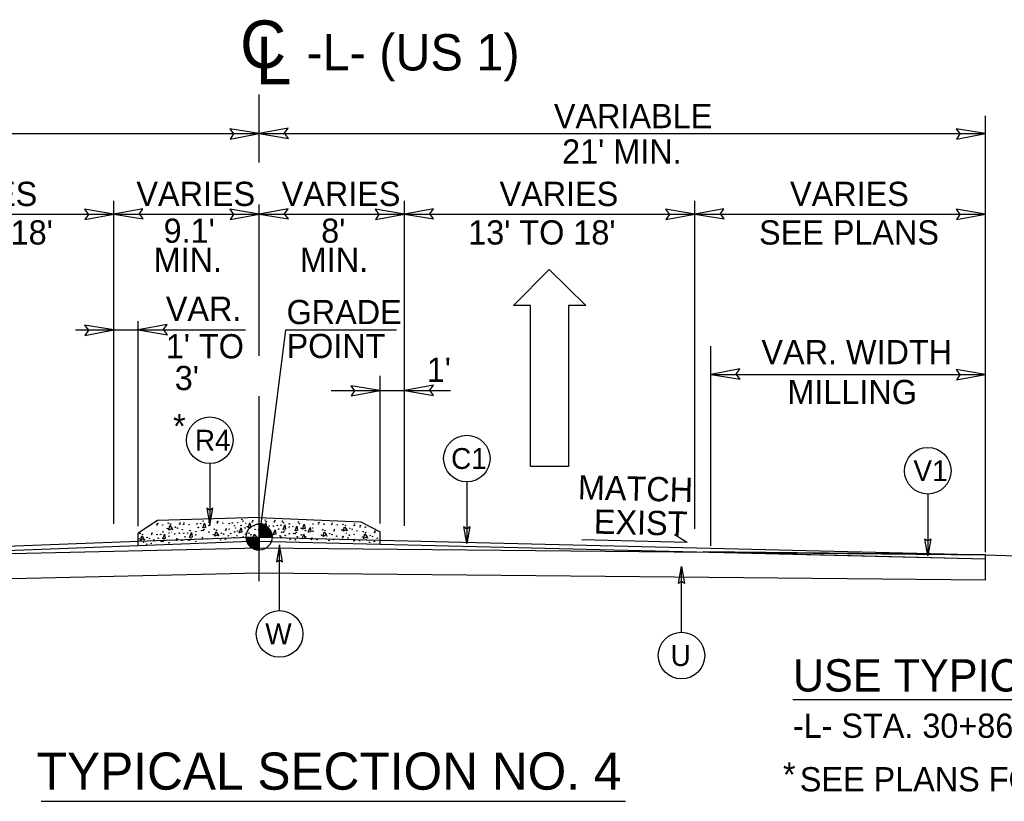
# Model space of a CAD drawing. Extents: x 573748 to 574632, y -54663 to -53209.
# Drawn here: x 573807.9 to 573868.9, y -53656.2 to -53607.8 of the extents above; entities that cross this region are included whole.
import ezdxf

# ---------------------------------------------------------------- set-up
doc = ezdxf.new("R2010")
doc.units = 0
for name, color, linetype in [('Prop Dimension', 7, 'Continuous'), ('Prop Dimension Text', 7, 'Continuous'), ('Prop Lane Arrow CELL', 7, 'Continuous'), ('Prop Terminator CELL', 7, 'Continuous'), ('Typical Arrow Superelevation CELL', 7, 'Continuous'), ('Typical Curb CELL', 7, 'Continuous'), ('Typical Grade Point Symbol CELL', 7, 'Continuous'), ('Typical ID Circle CELL', 7, 'Continuous'), ('Typical Pavement Slope CELL', 7, 'Continuous'), ('Typical Terminator CELL', 7, 'Continuous'), ('Typical Text Centerline CELL', 7, 'Continuous'), ('Typical Text General CELL', 7, 'Continuous'), ('Typical Text ID Circle CELL', 7, 'Continuous'), ('Typical Text Label CELL', 7, 'Continuous')]:
    doc.layers.add(name, color=color, linetype=linetype)

# ---------------------------------------------------------------- blocks, each defined once
blk = doc.blocks.new('CENTERLINE TEXT CL')
at = {"layer": 'Typical Text Centerline CELL'}
blk.add_text('C', height=1.64, dxfattribs=at).set_placement((-0.546, -0.261))
blk.add_text('L', height=1.641, rotation=359.9469, dxfattribs=at).set_placement((-0.001, -0.821))

msp = doc.modelspace()

# ---------------------------------------------------------------- linework, layer by layer
at = {"layer": 'Prop Dimension'}
for p, q in [((573822.721, -53616.626), (573822.721, -53612.419)), ((573867.721, -53640.778), (573867.721, -53613.746)), ((573867.721, -53638.046), (573867.721, -53613.746)), ((573777.721, -53614.846), (573822.721, -53614.846)), ((573822.721, -53614.846), (573867.721, -53614.846)), ((573813.721, -53639.007), (573813.721, -53619.001)), ((573831.721, -53639.143), (573831.721, -53619.001)), ((573849.721, -53639.33), (573849.721, -53619.001)), ((573822.721, -53628.608), (573822.721, -53619.243)), ((573795.721, -53619.827), (573813.721, -53619.827)), ((573813.721, -53619.827), (573822.721, -53619.827)), ((573822.721, -53619.827), (573831.721, -53619.827)), ((573831.721, -53619.827), (573849.721, -53619.827)), ((573849.721, -53619.827), (573867.721, -53619.827)), ((573811.343, -53627.007), (573821.876, -53627.007)), ((573815.221, -53639.155), (573815.221, -53626.465)), ((573850.708, -53640.379), (573850.708, -53628.013)), ((573830.221, -53639.004), (573830.221, -53629.853)), ((573850.708, -53629.758), (573867.721, -53629.758)), ((573822.721, -53642.56), (573822.721, -53631.099)), ((573827.184, -53630.764), (573834.582, -53630.764)), ((573822.721, -53638.617), (573816.429, -53638.815)), ((573822.721, -53638.617), (573829.014, -53638.889)), ((573816.429, -53638.815), (573815.221, -53639.605)), ((573829.014, -53638.889), (573830.221, -53639.506)), ((573815.221, -53640.375), (573815.221, -53639.605)), ((573830.221, -53640.276), (573830.221, -53639.506)), ((573822.721, -53640.094), (573815.221, -53640.375)), ((573822.721, -53640.094), (573830.221, -53640.276)), ((573777.721, -53641.521), (573822.721, -53640.499)), ((573822.721, -53640.499), (573867.721, -53640.927)), ((573867.721, -53640.927), (573850.242, -53640.761)), ((573850.242, -53640.761), (573867.721, -53641.184)), ((573867.721, -53640.927), (573883.644, -53641.498)), ((573867.721, -53642.484), (573867.721, -53640.927)), ((573867.721, -53641.184), (573867.721, -53640.927)), ((573777.721, -53643.077), (573822.721, -53642.056)), ((573822.721, -53642.056), (573867.721, -53642.484))]:
    msp.add_line(p, q, dxfattribs=at)
msp.add_lwpolyline([(573831.242, -53627.01), (573824.353, -53627.01), (573822.721, -53639.837)], dxfattribs=at)
at = {"layer": 'Prop Lane Arrow CELL'}
for p, q in [((573838.477, -53625.497), (573840.686, -53623.253)), ((573840.686, -53623.253), (573842.966, -53625.497)), ((573839.546, -53625.497), (573838.477, -53625.497)), ((573839.546, -53635.472), (573839.546, -53625.497)), ((573842.966, -53625.497), (573841.897, -53625.497)), ((573841.897, -53625.497), (573841.897, -53635.472)), ((573841.897, -53635.472), (573839.546, -53635.472))]:
    msp.add_line(p, q, dxfattribs=at)
at = {"layer": 'Prop Terminator CELL'}
for points in [[(573820.925, -53615.179), (573822.721, -53614.846), (573820.907, -53614.549), (573821.141, -53614.866)], [(573824.518, -53614.513), (573822.721, -53614.846), (573824.536, -53615.143), (573824.302, -53614.825)], [(573865.925, -53615.179), (573867.721, -53614.846), (573865.907, -53614.549), (573866.141, -53614.866)], [(573811.925, -53620.161), (573813.721, -53619.827), (573811.907, -53619.531), (573812.141, -53619.848)], [(573815.518, -53619.494), (573813.721, -53619.827), (573815.536, -53620.124), (573815.302, -53619.807)], [(573820.925, -53620.161), (573822.721, -53619.827), (573820.907, -53619.531), (573821.141, -53619.848)], [(573824.518, -53619.494), (573822.721, -53619.827), (573824.536, -53620.124), (573824.302, -53619.807)], [(573829.925, -53620.161), (573831.721, -53619.827), (573829.907, -53619.531), (573830.141, -53619.848)], [(573833.518, -53619.494), (573831.721, -53619.827), (573833.536, -53620.124), (573833.302, -53619.807)], [(573847.925, -53620.161), (573849.721, -53619.827), (573847.907, -53619.531), (573848.141, -53619.848)], [(573851.518, -53619.494), (573849.721, -53619.827), (573851.536, -53620.124), (573851.302, -53619.807)], [(573865.925, -53620.161), (573867.721, -53619.827), (573865.907, -53619.531), (573866.141, -53619.848)], [(573811.925, -53627.341), (573813.721, -53627.007), (573811.907, -53626.71), (573812.141, -53627.028)], [(573817.018, -53626.674), (573815.221, -53627.007), (573817.036, -53627.304), (573816.802, -53626.987)], [(573852.504, -53629.425), (573850.708, -53629.758), (573852.522, -53630.055), (573852.288, -53629.738)], [(573865.925, -53630.092), (573867.721, -53629.758), (573865.907, -53629.462), (573866.141, -53629.779)], [(573828.425, -53631.097), (573830.221, -53630.764), (573828.407, -53630.467), (573828.641, -53630.784)], [(573833.518, -53630.431), (573831.721, -53630.764), (573833.536, -53631.061), (573833.302, -53630.744)]]:
    msp.add_lwpolyline(points, close=True, dxfattribs=at)
at = {"layer": 'Typical Arrow Superelevation CELL'}
for q in [(573848.465, -53639.688), (573842.724, -53640.01)]:
    msp.add_line((573849.247, -53640.164), q, dxfattribs=at)
at = {"layer": 'Typical Curb CELL'}
for p, q in [((573817.122, -53639.406), (573817.199, -53639.127)), ((573817.199, -53639.127), (573817.333, -53639.3)), ((573819.239, -53639.272), (573819.347, -53638.979)), ((573819.393, -53639.249), (573819.239, -53639.272)), ((573819.347, -53638.979), (573819.393, -53639.249)), ((573821.493, -53639.564), (573821.601, -53639.271)), ((573821.601, -53639.271), (573821.648, -53639.541)), ((573822.034, -53639.252), (573822.142, -53638.959)), ((573822.188, -53639.229), (573822.034, -53639.252)), ((573822.142, -53638.959), (573822.188, -53639.229)), ((573823.021, -53639.251), (573823.128, -53638.958)), ((573823.175, -53639.228), (573823.021, -53639.251)), ((573823.128, -53638.958), (573823.175, -53639.228)), ((573824.209, -53639.372), (573824.316, -53639.079)), ((573824.316, -53639.079), (573824.363, -53639.349)), ((573824.95, -53639.459), (573825.057, -53639.166)), ((573825.057, -53639.166), (573825.104, -53639.436)), ((573825.411, -53639.338), (573825.519, -53639.045)), ((573825.519, -53639.045), (573825.566, -53639.315)), ((573825.77, -53639.54), (573825.878, -53639.247)), ((573825.878, -53639.247), (573825.925, -53639.517)), ((573827.937, -53639.479), (573828.014, -53639.2)), ((573828.014, -53639.2), (573828.148, -53639.373)), ((573815.372, -53640.04), (573815.449, -53639.761)), ((573815.449, -53639.761), (573815.583, -53639.934)), ((573816.752, -53639.941), (573816.859, -53639.648)), ((573816.859, -53639.648), (573816.906, -53639.918)), ((573817.333, -53639.3), (573817.122, -53639.406)), ((573818.418, -53639.856), (573818.525, -53639.563)), ((573818.572, -53639.833), (573818.418, -53639.856)), ((573818.525, -53639.563), (573818.572, -53639.833)), ((573819.97, -53639.782), (573820.047, -53639.503)), ((573820.181, -53639.676), (573819.97, -53639.782)), ((573820.047, -53639.503), (573820.181, -53639.676)), ((573821.648, -53639.541), (573821.493, -53639.564)), ((573822.342, -53639.943), (573822.419, -53639.664)), ((573822.553, -53639.837), (573822.342, -53639.943)), ((573822.419, -53639.664), (573822.553, -53639.837)), ((573823.601, -53639.688), (573823.709, -53639.395)), ((573823.755, -53639.665), (573823.601, -53639.688)), ((573823.709, -53639.395), (573823.755, -53639.665)), ((573824.363, -53639.349), (573824.209, -53639.372)), ((573825.104, -53639.436), (573824.95, -53639.459)), ((573825.392, -53639.942), (573825.5, -53639.649)), ((573825.566, -53639.315), (573825.411, -53639.338)), ((573825.5, -53639.649), (573825.546, -53639.919)), ((573825.925, -53639.517), (573825.77, -53639.54)), ((573826.685, -53639.809), (573826.762, -53639.53)), ((573826.896, -53639.703), (573826.685, -53639.809)), ((573826.762, -53639.53), (573826.896, -53639.703)), ((573828.148, -53639.373), (573827.937, -53639.479)), ((573829.196, -53639.924), (573829.273, -53639.645)), ((573829.407, -53639.818), (573829.196, -53639.924)), ((573829.273, -53639.645), (573829.407, -53639.818)), ((573815.583, -53639.934), (573815.372, -53640.04)), ((573816.906, -53639.918), (573816.752, -53639.941)), ((573825.546, -53639.919), (573825.392, -53639.942))]:
    msp.add_line(p, q, dxfattribs=at)
for centre in [(573816.401, -53639.081), (573816.429, -53638.993), (573816.739, -53639.09), (573817.095, -53638.979), (573817.242, -53639.038), (573817.525, -53639.223), (573817.671, -53639.281), (573817.801, -53639.041), (573817.829, -53638.953), (573818.036, -53639.057), (573818.064, -53638.97), (573818.374, -53639.067), (573818.877, -53639.017), (573818.957, -53639.242), (573819.102, -53639.006), (573819.256, -53638.851), (573819.615, -53639.119), (573819.622, -53638.916), (573820.132, -53638.958), (573820.16, -53638.87), (573820.47, -53638.967), (573820.872, -53639.003), (573821.056, -53638.961), (573821.198, -53639.135), (573821.26, -53639.274), (573821.397, -53638.944), (573821.599, -53639.115), (573821.648, -53638.745), (573821.716, -53638.843), (573821.849, -53639.269), (573821.897, -53638.986), (573821.998, -53639.19), (573822.301, -53638.896), (573822.329, -53638.809), (573822.414, -53639.136), (573822.721, -53638.993), (573822.921, -53639.01), (573823.099, -53638.783), (573823.168, -53638.881), (573823.331, -53639.157), (573823.605, -53639.156), (573823.665, -53638.896), (573823.693, -53638.809), (573823.847, -53639.116), (573824.072, -53639.105), (573824.157, -53638.852), (573824.226, -53638.95), (573824.585, -53639.218), (573824.592, -53639.015), (573824.813, -53639.192), (573825.145, -53638.914), (573825.214, -53639.013), (573825.326, -53639.292), (573826.038, -53639.276), (573826.055, -53639.028), (573826.397, -53639.028), (573826.425, -53638.941), (573826.735, -53639.038), (573827.222, -53639.068), (573827.25, -53638.981), (573827.56, -53639.078), (573827.91, -53639.052), (573828.057, -53639.111), (573828.616, -53639.114), (573828.644, -53639.026), (573828.968, -53639.213), (573828.996, -53639.125), (573829.305, -53639.223), (573815.346, -53639.614), (573815.493, -53639.672), (573815.775, -53639.857), (573816.052, -53639.675), (573816.08, -53639.588), (573816.389, -53639.685), (573816.615, -53639.674), (573816.768, -53639.519), (573817.039, -53639.313), (573817.128, -53639.787), (573817.135, -53639.584), (573817.353, -53639.367), (573817.491, -53639.643), (573817.783, -53639.595), (573817.962, -53639.378), (573818.055, -53639.6), (573818.136, -53639.826), (573818.281, -53639.589), (573818.434, -53639.434), (573818.794, -53639.702), (573818.801, -53639.5), (573819.149, -53639.438), (573819.216, -53639.854), (573819.246, -53639.438), (573819.309, -53639.361), (573819.62, -53639.528), (573819.887, -53639.689), (573819.944, -53639.356), (573820.09, -53639.414), (573820.201, -53639.743), (573820.373, -53639.599), (573820.519, -53639.658), (573820.649, -53639.417), (573820.677, -53639.33), (573820.81, -53639.754), (573820.867, -53639.35), (573820.959, -53639.623), (573821.172, -53639.872), (573821.203, -53639.513), (573821.343, -53639.756), (573821.395, -53639.462), (573821.732, -53639.813), (573821.883, -53639.656), (573822.09, -53639.591), (573822.214, -53639.696), (573822.464, -53639.358), (573822.684, -53639.389), (573822.774, -53639.796), (573822.787, -53639.643), (573822.957, -53639.398), (573823.007, -53639.764), (573823.079, -53639.842), (573823.118, -53639.536), (573823.345, -53639.782), (573823.41, -53639.489), (573823.524, -53639.722), (573823.597, -53639.875), (573823.927, -53639.341), (573824.008, -53639.765), (573824.08, -53639.843), (573824.119, -53639.537), (573824.216, -53639.537), (573824.279, -53639.46), (573824.342, -53639.734), (573824.59, -53639.628), (573824.86, -53639.624), (573824.957, -53639.624), (573825.02, -53639.548), (573825.083, -53639.822), (573825.33, -53639.702), (573825.583, -53639.43), (573825.608, -53639.818), (573825.991, -53639.898), (573826.066, -53639.474), (573826.603, -53639.716), (573826.659, -53639.383), (573826.806, -53639.441), (573826.917, -53639.77), (573827.088, -53639.626), (573827.235, -53639.685), (573827.365, -53639.444), (573827.393, -53639.357), (573827.525, -53639.781), (573827.854, -53639.386), (573827.893, -53639.88), (573827.921, -53639.793), (573828.168, -53639.44), (573828.231, -53639.89), (573828.306, -53639.716), (573828.339, -53639.296), (573828.486, -53639.354), (573828.598, -53639.668), (573828.776, -53639.451), (573829.113, -53639.832), (573829.169, -53639.498), (573829.316, -53639.557), (573829.427, -53639.885), (573829.599, -53639.741), (573829.745, -53639.8), (573829.875, -53639.559), (573829.903, -53639.472), (573830.036, -53639.896), (573815.29, -53639.947), (573815.604, -53640.001), (573815.742, -53640.277), (573815.922, -53639.916), (573816.033, -53640.23), (573816.212, -53640.012), (573816.47, -53639.91), (573816.662, -53640.106), (573816.759, -53640.106), (573816.822, -53640.03), (573817.133, -53640.197), (573817.606, -53640.033), (573817.635, -53639.946), (573817.944, -53640.043), (573818.328, -53640.022), (573818.425, -53640.022), (573818.488, -53639.945), (573818.798, -53640.112), (573819.188, -53639.941), (573819.525, -53639.951), (573820.339, -53640.019), (573820.631, -53639.972), (573824.631, -53639.997), (573824.659, -53639.909), (573824.968, -53640.006), (573825.963, -53639.985), (573826.301, -53639.995), (573827.055, -53640.046), (573827.346, -53639.999), (573828.604, -53640.064), (573828.632, -53639.977), (573828.941, -53640.074), (573829.565, -53640.161), (573829.857, -53640.114)]:
    msp.add_ellipse(centre, major_axis=(0.0001, 0.0192), ratio=0.533333, dxfattribs=at)
for centre in [(573817.305, -53639.548), (573828.12, -53639.621), (573815.556, -53640.182), (573820.154, -53639.925), (573826.869, -53639.951), (573829.379, -53640.067)]:
    msp.add_ellipse(centre, major_axis=(-0.0001, -0.0219), ratio=0.533333, start_param=2.050606, end_param=4.270718, dxfattribs=at)
at = {"layer": 'Typical Grade Point Symbol CELL'}
for p, q in [((573822.721, -53639.837), (573822.721, -53639.031)), ((573821.916, -53639.837), (573822.721, -53639.837)), ((573822.719, -53640.643), (573822.721, -53639.837)), ((573822.721, -53639.837), (573822.719, -53640.643)), ((573823.527, -53639.837), (573822.721, -53639.837))]:
    msp.add_line(p, q, dxfattribs=at)
for points in [[(573822.728, -53639.031), (573822.728, -53639.031), (573822.728, -53639.837)], [(573822.745, -53639.031), (573822.745, -53639.837)], [(573822.761, -53639.033), (573822.761, -53639.837)], [(573822.777, -53639.033), (573822.777, -53639.837)], [(573822.793, -53639.035), (573822.793, -53639.837)], [(573822.809, -53639.037), (573822.809, -53639.837)], [(573822.825, -53639.038), (573822.825, -53639.837)], [(573822.841, -53639.04), (573822.841, -53639.837)], [(573822.857, -53639.042), (573822.857, -53639.837)], [(573822.873, -53639.046), (573822.873, -53639.837)], [(573822.89, -53639.049), (573822.89, -53639.837)], [(573822.906, -53639.053), (573822.906, -53639.837)], [(573822.922, -53639.056), (573822.922, -53639.837)], [(573822.938, -53639.062), (573822.938, -53639.837)], [(573822.954, -53639.065), (573822.954, -53639.837)], [(573822.97, -53639.071), (573822.97, -53639.837)], [(573822.986, -53639.076), (573822.986, -53639.837)], [(573823.002, -53639.081), (573823.002, -53639.837)], [(573823.018, -53639.089), (573823.018, -53639.837)], [(573823.035, -53639.096), (573823.035, -53639.837)], [(573823.051, -53639.103), (573823.051, -53639.837)], [(573823.067, -53639.11), (573823.067, -53639.837)], [(573823.083, -53639.117), (573823.083, -53639.837)], [(573823.099, -53639.126), (573823.099, -53639.837)], [(573823.115, -53639.135), (573823.115, -53639.837)], [(573823.131, -53639.144), (573823.131, -53639.837)], [(573823.147, -53639.153), (573823.147, -53639.837)], [(573823.163, -53639.164), (573823.163, -53639.837)], [(573823.18, -53639.175), (573823.18, -53639.837)], [(573823.196, -53639.187), (573823.196, -53639.837)], [(573823.212, -53639.198), (573823.212, -53639.837)], [(573823.228, -53639.21), (573823.228, -53639.837)], [(573823.244, -53639.225), (573823.244, -53639.837)], [(573823.26, -53639.239), (573823.26, -53639.837)], [(573823.276, -53639.253), (573823.276, -53639.837)], [(573823.292, -53639.269), (573823.292, -53639.837)], [(573821.919, -53639.837), (573821.919, -53639.925)], [(573821.935, -53639.837), (573821.935, -53640.02)], [(573821.951, -53639.837), (573821.951, -53640.077)], [(573821.968, -53639.837), (573821.968, -53640.125)], [(573821.984, -53639.837), (573821.984, -53640.163)], [(573822, -53639.837), (573822, -53640.197)], [(573822.016, -53639.837), (573822.016, -53640.227)], [(573822.032, -53639.837), (573822.032, -53640.256)], [(573822.048, -53639.837), (573822.048, -53640.281)], [(573822.064, -53639.837), (573822.064, -53640.304)], [(573822.08, -53639.837), (573822.08, -53640.326)], [(573822.096, -53639.837), (573822.096, -53640.345)], [(573822.113, -53639.837), (573822.113, -53640.365)], [(573822.129, -53639.837), (573822.129, -53640.383)], [(573822.145, -53639.837), (573822.145, -53640.401)], [(573822.161, -53639.837), (573822.161, -53640.417)], [(573822.177, -53639.837), (573822.177, -53640.431)], [(573822.193, -53639.837), (573822.193, -53640.446)], [(573822.209, -53639.837), (573822.209, -53640.46)], [(573822.225, -53639.837), (573822.225, -53640.472)], [(573822.241, -53639.837), (573822.241, -53640.485)], [(573822.258, -53639.837), (573822.258, -53640.496)], [(573822.274, -53639.837), (573822.274, -53640.507)], [(573822.29, -53639.837), (573822.29, -53640.517)], [(573822.306, -53639.837), (573822.306, -53640.528)], [(573822.322, -53639.837), (573822.322, -53640.537)], [(573822.338, -53639.837), (573822.338, -53640.546)], [(573822.354, -53639.837), (573822.354, -53640.555)], [(573822.37, -53639.837), (573822.37, -53640.562)], [(573822.387, -53639.837), (573822.387, -53640.569)], [(573822.403, -53639.837), (573822.403, -53640.576)], [(573822.419, -53639.837), (573822.419, -53640.583)], [(573822.435, -53639.837), (573822.435, -53640.591)], [(573822.451, -53639.837), (573822.451, -53640.596)], [(573822.467, -53639.837), (573822.467, -53640.601)], [(573822.483, -53639.837), (573822.483, -53640.607)], [(573822.499, -53639.837), (573822.499, -53640.61)], [(573822.515, -53639.837), (573822.515, -53640.616)], [(573822.532, -53639.837), (573822.532, -53640.619)], [(573822.548, -53639.837), (573822.548, -53640.623)], [(573822.564, -53639.837), (573822.564, -53640.626)], [(573822.58, -53639.837), (573822.58, -53640.63)], [(573822.596, -53639.837), (573822.596, -53640.632)], [(573822.612, -53639.837), (573822.612, -53640.635)], [(573822.628, -53639.837), (573822.628, -53640.637)], [(573822.644, -53639.837), (573822.644, -53640.639)], [(573822.66, -53639.837), (573822.66, -53640.641)], [(573822.677, -53639.837), (573822.677, -53640.641)], [(573822.693, -53639.837), (573822.693, -53640.643)], [(573822.709, -53639.837), (573822.709, -53640.643), (573822.709, -53640.643)], [(573823.308, -53639.286), (573823.308, -53639.837)], [(573823.325, -53639.303), (573823.325, -53639.837)], [(573823.341, -53639.323), (573823.341, -53639.837)], [(573823.357, -53639.343), (573823.357, -53639.837)], [(573823.373, -53639.364), (573823.373, -53639.837)], [(573823.389, -53639.388), (573823.389, -53639.837)], [(573823.405, -53639.413), (573823.405, -53639.837)], [(573823.421, -53639.439), (573823.421, -53639.837)], [(573823.437, -53639.468), (573823.437, -53639.837)], [(573823.453, -53639.502), (573823.453, -53639.837)], [(573823.47, -53639.54), (573823.47, -53639.837)], [(573823.486, -53639.585), (573823.486, -53639.837)], [(573823.502, -53639.64), (573823.502, -53639.837)], [(573823.518, -53639.722), (573823.518, -53639.837)]]:
    msp.add_lwpolyline(points, dxfattribs=at)
msp.add_circle((573822.72, -53639.837), 0.806, dxfattribs=at)
for start, end in [(359.99048, 89.99048), (179.99048, 269.99048)]:
    msp.add_arc((573822.72, -53639.837), 0.806, start, end, dxfattribs=at)
at = {"layer": 'Typical ID Circle CELL'}
for p, q in [((573819.666, -53635.284), (573819.666, -53639.11)), ((573835.591, -53636.416), (573835.591, -53640.243)), ((573864.153, -53637.17), (573864.153, -53640.997)), ((573823.99, -53644.395), (573823.99, -53640.312)), ((573848.891, -53645.738), (573848.891, -53641.655))]:
    msp.add_line(p, q, dxfattribs=at)
for centre in [(573819.666, -53633.841), (573835.591, -53634.974), (573864.153, -53635.728), (573823.99, -53645.838), (573848.891, -53647.181)]:
    msp.add_circle(centre, 1.443, dxfattribs=at)
at = {"layer": 'Typical Pavement Slope CELL'}
for p, q in [((573822.721, -53639.837), (573815.221, -53640.118)), ((573822.721, -53639.837), (573830.221, -53640.019)), ((573815.221, -53640.118), (573777.721, -53641.521)), ((573815.221, -53640.375), (573777.721, -53641.778)), ((573830.221, -53640.019), (573867.721, -53640.927)), ((573830.221, -53640.276), (573867.721, -53641.184))]:
    msp.add_line(p, q, dxfattribs=at)
at = {"layer": 'Typical Terminator CELL'}
for points in [[(573819.485, -53638.056), (573819.666, -53639.11), (573819.854, -53638.05), (573819.666, -53638.185)], [(573835.773, -53639.188), (573835.591, -53640.243), (573835.403, -53639.182), (573835.591, -53639.317)], [(573824.171, -53641.366), (573823.99, -53640.312), (573823.802, -53641.372), (573823.99, -53641.237)], [(573864.335, -53639.942), (573864.153, -53640.997), (573863.965, -53639.936), (573864.153, -53640.071)], [(573848.709, -53642.709), (573848.891, -53641.655), (573849.078, -53642.715), (573848.891, -53642.581)]]:
    msp.add_lwpolyline(points, close=True, dxfattribs=at)
at = {"layer": 'Typical Text General CELL'}
msp.add_line((573855.791, -53649.901), (573894.17, -53649.901), dxfattribs=at)
at = {"layer": 'Typical Text Label CELL'}
msp.add_line((573809.221, -53656.206), (573845.428, -53656.206), dxfattribs=at)

# ---------------------------------------------------------------- block references
at = {"layer": 'Prop Dimension', "xscale": 1.8000000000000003, "yscale": 1.8000000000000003}
msp.add_blockref('CENTERLINE TEXT CL', (573822.525, -53610.314), dxfattribs=at)

# ---------------------------------------------------------------- texts
at = {"layer": 'Prop Dimension Text'}
for s, height, p in [('-L- (US 1)', 2.25, (573825.652, -53610.931)), ('VARIABLE', 1.5, (573840.985, -53614.507)), ("21' MIN.", 1.5, (573841.494, -53616.701)), ('VARIES', 1.5, (573801.618, -53619.326)), ('VARIES', 1.5, (573815.118, -53619.326)), ('VARIES', 1.5, (573824.118, -53619.326)), ('VARIES', 1.5, (573837.618, -53619.326)), ('VARIES', 1.5, (573855.618, -53619.326)), ("16.5' TO 18'", 1.5, (573799.14, -53621.714)), ("9.1'", 1.5, (573816.805, -53621.608)), ("8'", 1.5, (573826.568, -53621.608)), ("13' TO 18'", 1.5, (573835.677, -53621.714)), ('SEE PLANS', 1.5, (573853.697, -53621.714)), ('MIN.', 1.5, (573816.192, -53623.408)), ('MIN.', 1.5, (573825.245, -53623.408)), ('VAR.', 1.5, (573816.941, -53626.444)), ('GRADE', 1.5, (573824.424, -53626.647)), ("1' TO", 1.5, (573816.937, -53628.766)), ('POINT', 1.5, (573824.424, -53628.747)), ('VAR. WIDTH', 1.5, (573853.844, -53629.128)), ("1'", 1.5, (573833.106, -53630.221)), (" 3'", 1.5, (573816.937, -53630.732)), ('MILLING', 1.5, (573855.457, -53631.598)), ('*', 1.5, (573817.389, -53633.714)), ('TYPICAL SECTION NO. 4', 2.3, (573808.939, -53655.486)), ('*', 1.5, (573855.179, -53655.297))]:
    msp.add_text(s, height=height, dxfattribs=at).set_placement(p)
for s, p in [('MATCH', (573842.462, -53637.498)), ('EXIST', (573843.447, -53639.622))]:
    msp.add_text(s, height=1.5, rotation=358.65063, dxfattribs=at).set_placement(p)
at = {"layer": 'Typical Text General CELL'}
for s, height, p in [('USE TYPICAL SECTION NO. 4', 2, (573855.791, -53649.404)), ('-L- STA. 30+86.00 TO STA. 31+44.17', 1.5, (573855.791, -53652.274)), ('SEE PLANS FOR LIMITS OF CONC. ISLAND', 1.5, (573856.223, -53655.589))]:
    msp.add_text(s, height=height, dxfattribs=at).set_placement(p)
at = {"layer": 'Typical Text ID Circle CELL'}
for s, height, p in [('R4', 1.2912, (573818.744, -53634.484)), ('C1', 1.2912, (573834.618, -53635.616)), ('V1', 1.2912, (573863.264, -53636.371)), ('W', 1.291, (573823.105, -53646.481)), ('U', 1.291, (573848.22, -53647.824))]:
    msp.add_text(s, height=height, dxfattribs=at).set_placement(p)

doc.saveas('drawing.dxf')
